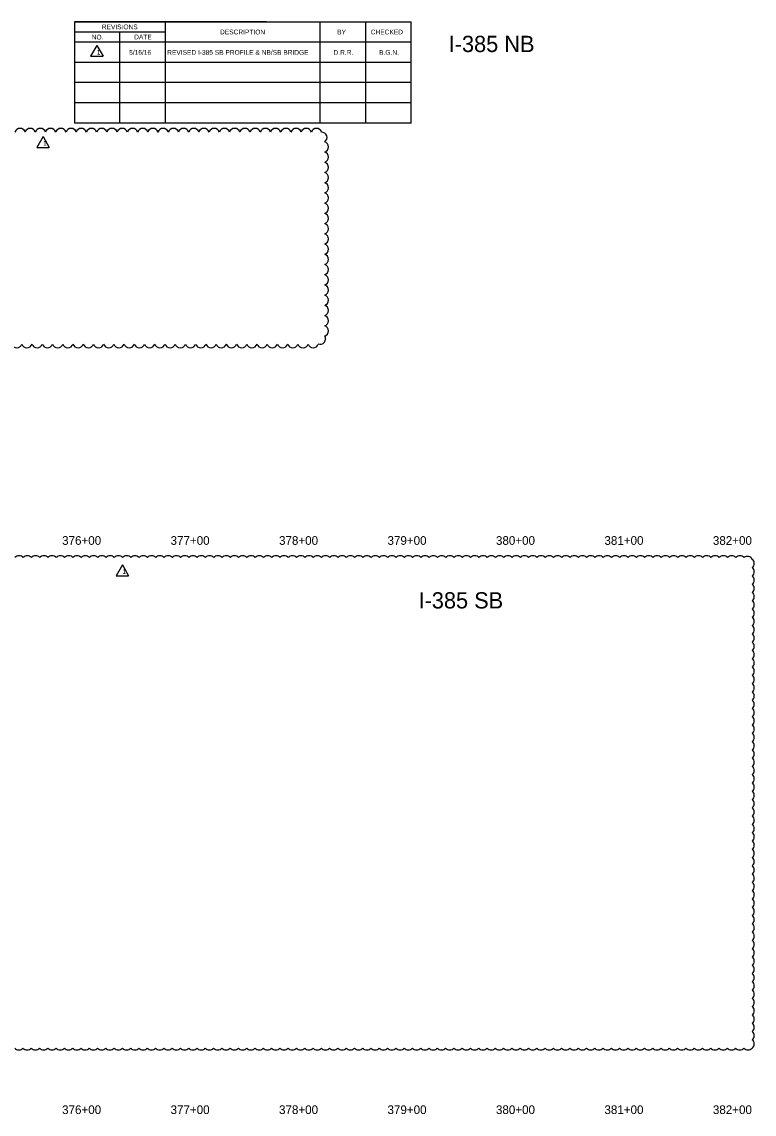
# Model space of a CAD drawing. Extents: x 1617657 to 1619318, y 1076167 to 1077194.
# Drawn here: x 1618080 to 1618756, y 1076167 to 1077175 of the extents above; entities that cross this region are included whole.
import ezdxf

# ---------------------------------------------------------------- set-up
doc = ezdxf.new("R2010")
doc.units = 0
doc.layers.add('Default', color=7, linetype='Continuous')
doc.layers.add('RD_SHT_TX', color=7, linetype='Continuous')

msp = doc.modelspace()

# ---------------------------------------------------------------- linework, layer by layer
at = {"layer": 'RD_SHT_TX'}
for p, q in [((1618128.9, 1077174.7), (1618439.5, 1077174.7)), ((1618306.1, 1077174.7), (1618128.9, 1077174.7)), ((1618128.9, 1077174.7), (1618128.9, 1077081.2)), ((1618212.9, 1077081.2), (1618212.9, 1077174.7)), ((1618355.5, 1077081.2), (1618355.5, 1077174.7)), ((1618397.5, 1077081.2), (1618397.5, 1077174.7)), ((1618439.5, 1077081.2), (1618439.5, 1077174.7)), ((1618212.9, 1077165.3), (1618128.9, 1077165.3)), ((1618170.9, 1077081.2), (1618170.9, 1077165.3)), ((1618439.5, 1077156), (1618128.9, 1077156)), ((1618149.6, 1077153), (1618143.9, 1077142.9)), ((1618149.6, 1077153), (1618155.3, 1077142.9)), ((1618143.9, 1077142.9), (1618155.3, 1077142.9)), ((1618439.5, 1077137.3), (1618128.9, 1077137.3)), ((1618439.5, 1077118.6), (1618128.9, 1077118.6)), ((1618439.5, 1077099.9), (1618128.9, 1077099.9)), ((1618439.5, 1077081.2), (1618128.9, 1077081.2)), ((1618100, 1077068.9), (1618094.3, 1077058.8)), ((1618100, 1077068.9), (1618105.7, 1077058.8)), ((1618094.3, 1077058.8), (1618105.7, 1077058.8)), ((1618173.2, 1076673.9), (1618167.5, 1076663.7)), ((1618173.2, 1076673.9), (1618178.9, 1076663.7)), ((1618167.5, 1076663.7), (1618178.9, 1076663.7))]:
    msp.add_line(p, q, dxfattribs=at)
for centre, radius, start, end in [((1618078.8, 1077071.5), 4.94, 17.5, 162.5), ((1618088.2, 1077071.5), 4.94, 17.5, 162.5), ((1618097.6, 1077071.5), 4.94, 17.5, 162.5), ((1618107, 1077071.5), 4.94, 17.5, 162.5), ((1618116.5, 1077071.5), 4.94, 17.5, 162.5), ((1618125.9, 1077071.5), 4.94, 17.5, 162.5), ((1618135.3, 1077071.5), 4.94, 17.5, 162.5), ((1618144.7, 1077071.5), 4.94, 17.5, 162.5), ((1618154.2, 1077071.5), 4.94, 17.5, 162.5), ((1618163.6, 1077071.5), 4.94, 17.5, 162.5), ((1618173, 1077071.5), 4.94, 17.5, 162.5), ((1618182.5, 1077071.5), 4.94, 17.5, 162.5), ((1618191.9, 1077071.5), 4.94, 17.5, 162.5), ((1618201.3, 1077071.5), 4.94, 17.5, 162.5), ((1618210.7, 1077071.5), 4.94, 17.5, 162.5), ((1618220.2, 1077071.5), 4.94, 17.5, 162.5), ((1618229.6, 1077071.5), 4.94, 17.5, 162.5), ((1618239, 1077071.5), 4.94, 17.5, 162.5), ((1618248.4, 1077071.5), 4.94, 17.5, 162.5), ((1618257.9, 1077071.5), 4.94, 17.5, 162.5), ((1618267.3, 1077071.5), 4.94, 17.5, 162.5), ((1618276.7, 1077071.5), 4.94, 17.5, 162.5), ((1618286.1, 1077071.5), 4.94, 17.5, 162.5), ((1618295.6, 1077071.5), 4.94, 17.5, 162.5), ((1618305, 1077071.5), 4.94, 17.5, 162.5), ((1618314.4, 1077071.5), 4.94, 17.5, 162.5), ((1618323.9, 1077071.5), 4.94, 17.5, 162.5), ((1618333.3, 1077071.5), 4.94, 17.5, 162.5), ((1618342.7, 1077071.5), 4.94, 17.5, 162.5), ((1618352.1, 1077071.5), 4.94, 17.5, 162.5), ((1618356.9, 1077068), 4.94, 305.5066, 90.5066), ((1618358.3, 1077059.3), 4.94, 287.5, 72.5), ((1618358.3, 1077049.9), 4.94, 287.5, 72.5), ((1618358.3, 1077040.4), 4.94, 287.5, 72.5), ((1618358.3, 1077031), 4.94, 287.5, 72.5), ((1618358.3, 1077021.6), 4.94, 287.5, 72.5), ((1618358.3, 1077012.2), 4.94, 287.5, 72.5), ((1618358.3, 1077002.7), 4.94, 287.5, 72.5), ((1618358.3, 1076993.3), 4.94, 287.5, 72.5), ((1618358.3, 1076983.9), 4.94, 287.5, 72.5), ((1618358.3, 1076974.5), 4.94, 287.5, 72.5), ((1618358.3, 1076965), 4.94, 287.5, 72.5), ((1618358.3, 1076955.6), 4.94, 287.5, 72.5), ((1618358.3, 1076946.2), 4.94, 287.5, 72.5), ((1618358.3, 1076936.7), 4.94, 287.5, 72.5), ((1618358.3, 1076927.3), 4.94, 287.5, 72.5), ((1618358.3, 1076917.9), 4.94, 287.5, 72.5), ((1618358.3, 1076908.5), 4.94, 287.5, 72.5), ((1618358.3, 1076899), 4.94, 287.5, 72.5), ((1618358.3, 1076889.6), 4.94, 287.5, 72.5), ((1618355.6, 1076882.2), 4.94, 248.7452, 33.7452), ((1618075.8, 1076879), 4.94, 197.5, 342.5), ((1618085.2, 1076879), 4.94, 197.5, 342.5), ((1618094.6, 1076879), 4.94, 197.5, 342.5), ((1618104.1, 1076879), 4.94, 197.5, 342.5), ((1618113.5, 1076879), 4.94, 197.5, 342.5), ((1618122.9, 1076879), 4.94, 197.5, 342.5), ((1618132.3, 1076879), 4.94, 197.5, 342.5), ((1618141.8, 1076879), 4.94, 197.5, 342.5), ((1618151.2, 1076879), 4.94, 197.5, 342.5), ((1618160.6, 1076879), 4.94, 197.5, 342.5), ((1618170, 1076879), 4.94, 197.5, 342.5), ((1618179.5, 1076879), 4.94, 197.5, 342.5), ((1618188.9, 1076879), 4.94, 197.5, 342.5), ((1618198.3, 1076879), 4.94, 197.5, 342.5), ((1618207.7, 1076879), 4.94, 197.5, 342.5), ((1618217.2, 1076879), 4.94, 197.5, 342.5), ((1618226.6, 1076879), 4.94, 197.5, 342.5), ((1618236, 1076879), 4.94, 197.5, 342.5), ((1618245.5, 1076879), 4.94, 197.5, 342.5), ((1618254.9, 1076879), 4.94, 197.5, 342.5), ((1618264.3, 1076879), 4.94, 197.5, 342.5), ((1618273.7, 1076879), 4.94, 197.5, 342.5), ((1618283.2, 1076879), 4.94, 197.5, 342.5), ((1618292.6, 1076879), 4.94, 197.5, 342.5), ((1618302, 1076879), 4.94, 197.5, 342.5), ((1618311.4, 1076879), 4.94, 197.5, 342.5), ((1618320.9, 1076879), 4.94, 197.5, 342.5), ((1618330.3, 1076879), 4.94, 197.5, 342.5), ((1618339.7, 1076879), 4.94, 197.5, 342.5), ((1618349.1, 1076879), 4.94, 197.5, 342.5), ((1618077.9, 1076677.3), 4.99, 40, 140), ((1618085.5, 1076677.3), 4.99, 40, 140), ((1618093.1, 1076677.3), 4.99, 40, 140), ((1618100.8, 1076677.3), 4.99, 40, 140), ((1618108.4, 1076677.3), 4.99, 40, 140), ((1618116.1, 1076677.3), 4.99, 40, 140), ((1618123.7, 1076677.3), 4.99, 40, 140), ((1618131.3, 1076677.3), 4.99, 40, 140), ((1618139, 1076677.3), 4.99, 40, 140), ((1618146.6, 1076677.3), 4.99, 40, 140), ((1618154.3, 1076677.3), 4.99, 40, 140), ((1618161.9, 1076677.3), 4.99, 40, 140), ((1618169.5, 1076677.3), 4.99, 40, 140), ((1618177.2, 1076677.3), 4.99, 40, 140), ((1618184.8, 1076677.3), 4.99, 40, 140), ((1618192.5, 1076677.3), 4.99, 40, 140), ((1618200.1, 1076677.3), 4.99, 40, 140), ((1618207.7, 1076677.3), 4.99, 40, 140), ((1618215.4, 1076677.3), 4.99, 40, 140), ((1618223, 1076677.3), 4.99, 40, 140), ((1618230.7, 1076677.3), 4.99, 40, 140), ((1618238.3, 1076677.3), 4.99, 40, 140), ((1618245.9, 1076677.3), 4.99, 40, 140), ((1618253.6, 1076677.3), 4.99, 40, 140), ((1618261.2, 1076677.3), 4.99, 40, 140), ((1618268.9, 1076677.3), 4.99, 40, 140), ((1618276.5, 1076677.3), 4.99, 40, 140), ((1618284.1, 1076677.3), 4.99, 40, 140), ((1618291.8, 1076677.3), 4.99, 40, 140), ((1618299.4, 1076677.3), 4.99, 40, 140), ((1618307.1, 1076677.3), 4.99, 40, 140), ((1618314.7, 1076677.3), 4.99, 40, 140), ((1618322.3, 1076677.3), 4.99, 40, 140), ((1618330, 1076677.3), 4.99, 40, 140), ((1618337.6, 1076677.3), 4.99, 40, 140), ((1618345.3, 1076677.3), 4.99, 40, 140), ((1618352.9, 1076677.3), 4.99, 40, 140), ((1618360.5, 1076677.3), 4.99, 40, 140), ((1618368.2, 1076677.3), 4.99, 40, 140), ((1618375.8, 1076677.3), 4.99, 40, 140), ((1618383.5, 1076677.3), 4.99, 40, 140), ((1618391.1, 1076677.3), 4.99, 40, 140), ((1618398.7, 1076677.3), 4.99, 40, 140), ((1618406.4, 1076677.3), 4.99, 40, 140), ((1618414, 1076677.3), 4.99, 40, 140), ((1618421.7, 1076677.3), 4.99, 40, 140), ((1618429.3, 1076677.3), 4.99, 40, 140), ((1618436.9, 1076677.3), 4.99, 40, 140), ((1618444.6, 1076677.3), 4.99, 40, 140), ((1618452.2, 1076677.3), 4.99, 40, 140), ((1618459.9, 1076677.3), 4.99, 40, 140), ((1618467.5, 1076677.3), 4.99, 40, 140), ((1618475.1, 1076677.3), 4.99, 40, 140), ((1618482.8, 1076677.3), 4.99, 40, 140), ((1618490.4, 1076677.3), 4.99, 40, 140), ((1618498.1, 1076677.3), 4.99, 40, 140), ((1618505.7, 1076677.3), 4.99, 40, 140), ((1618513.3, 1076677.3), 4.99, 40, 140), ((1618521, 1076677.3), 4.99, 40, 140), ((1618528.6, 1076677.3), 4.99, 40, 140), ((1618536.3, 1076677.3), 4.99, 40, 140), ((1618543.9, 1076677.3), 4.99, 40, 140), ((1618551.5, 1076677.3), 4.99, 40, 140), ((1618559.2, 1076677.3), 4.99, 40, 140), ((1618566.8, 1076677.3), 4.99, 40, 140), ((1618574.5, 1076677.3), 4.99, 40, 140), ((1618582.1, 1076677.3), 4.99, 40, 140), ((1618589.8, 1076677.3), 4.99, 40, 140), ((1618597.4, 1076677.3), 4.99, 40, 140), ((1618605, 1076677.3), 4.99, 40, 140), ((1618612.7, 1076677.3), 4.99, 40, 140), ((1618620.3, 1076677.3), 4.99, 40, 140), ((1618628, 1076677.3), 4.99, 40, 140), ((1618635.6, 1076677.3), 4.99, 40, 140), ((1618643.2, 1076677.3), 4.99, 40, 140), ((1618650.9, 1076677.3), 4.99, 40, 140), ((1618658.5, 1076677.3), 4.99, 40, 140), ((1618666.2, 1076677.3), 4.99, 40, 140), ((1618673.8, 1076677.3), 4.99, 40, 140), ((1618681.4, 1076677.3), 4.99, 40, 140), ((1618689.1, 1076677.3), 4.99, 40, 140), ((1618696.7, 1076677.3), 4.99, 40, 140), ((1618704.4, 1076677.3), 4.99, 40, 140), ((1618712, 1076677.3), 4.99, 40, 140), ((1618719.6, 1076677.3), 4.99, 40, 140), ((1618727.3, 1076677.3), 4.99, 40, 140), ((1618734.9, 1076677.3), 4.99, 40, 140), ((1618742.6, 1076677.3), 4.99, 40, 140), ((1618749.5, 1076676.6), 4.99, 28.2006, 128.2006), ((1618750.7, 1076675.1), 4.99, 310, 50), ((1618750.7, 1076667.5), 4.99, 310, 50), ((1618750.7, 1076659.8), 4.99, 310, 50), ((1618750.7, 1076652.2), 4.99, 310, 50), ((1618750.7, 1076644.6), 4.99, 310, 50), ((1618750.7, 1076636.9), 4.99, 310, 50), ((1618750.7, 1076629.3), 4.99, 310, 50), ((1618750.7, 1076621.6), 4.99, 310, 50), ((1618750.7, 1076614), 4.99, 310, 50), ((1618750.7, 1076606.4), 4.99, 310, 50), ((1618750.7, 1076598.7), 4.99, 310, 50), ((1618750.7, 1076591.1), 4.99, 310, 50), ((1618750.7, 1076583.4), 4.99, 310, 50), ((1618750.7, 1076575.8), 4.99, 310, 50), ((1618750.7, 1076568.2), 4.99, 310, 50), ((1618750.7, 1076560.5), 4.99, 310, 50), ((1618750.7, 1076552.9), 4.99, 310, 50), ((1618750.7, 1076545.2), 4.99, 310, 50), ((1618750.7, 1076537.6), 4.99, 310, 50), ((1618750.7, 1076530), 4.99, 310, 50), ((1618750.7, 1076522.3), 4.99, 310, 50), ((1618750.7, 1076514.7), 4.99, 310, 50), ((1618750.7, 1076507), 4.99, 310, 50), ((1618750.7, 1076499.4), 4.99, 310, 50), ((1618750.7, 1076491.8), 4.99, 310, 50), ((1618750.7, 1076484.1), 4.99, 310, 50), ((1618750.7, 1076476.5), 4.99, 310, 50), ((1618750.7, 1076468.8), 4.99, 310, 50), ((1618750.7, 1076461.2), 4.99, 310, 50), ((1618750.7, 1076453.6), 4.99, 310, 50), ((1618750.7, 1076445.9), 4.99, 310, 50), ((1618750.7, 1076438.3), 4.99, 310, 50), ((1618750.7, 1076430.6), 4.99, 310, 50), ((1618750.7, 1076423), 4.99, 310, 50), ((1618750.7, 1076415.4), 4.99, 310, 50), ((1618750.7, 1076407.7), 4.99, 310, 50), ((1618750.7, 1076400.1), 4.99, 310, 50), ((1618750.7, 1076392.4), 4.99, 310, 50), ((1618750.7, 1076384.8), 4.99, 310, 50), ((1618750.7, 1076377.2), 4.99, 310, 50), ((1618750.7, 1076369.5), 4.99, 310, 50), ((1618750.7, 1076361.9), 4.99, 310, 50), ((1618750.7, 1076354.2), 4.99, 310, 50), ((1618750.7, 1076346.6), 4.99, 310, 50), ((1618750.7, 1076339), 4.99, 310, 50), ((1618750.7, 1076331.3), 4.99, 310, 50), ((1618750.7, 1076323.7), 4.99, 310, 50), ((1618750.7, 1076316), 4.99, 310, 50), ((1618750.7, 1076308.4), 4.99, 310, 50), ((1618750.7, 1076300.8), 4.99, 310, 50), ((1618750.7, 1076293.1), 4.99, 310, 50), ((1618750.7, 1076285.5), 4.99, 310, 50), ((1618750.7, 1076277.8), 4.99, 310, 50), ((1618750.7, 1076270.2), 4.99, 310, 50), ((1618750.7, 1076262.6), 4.99, 310, 50), ((1618750.7, 1076254.9), 4.99, 310, 50), ((1618750.7, 1076247.3), 4.99, 310, 50), ((1618750.7, 1076239.6), 4.99, 310, 50), ((1618750.7, 1076232), 4.99, 310, 50), ((1618077.7, 1076231.4), 4.99, 220, 320), ((1618085.3, 1076231.4), 4.99, 220, 320), ((1618093, 1076231.4), 4.99, 220, 320), ((1618100.6, 1076231.4), 4.99, 220, 320), ((1618108.3, 1076231.4), 4.99, 220, 320), ((1618115.9, 1076231.4), 4.99, 220, 320), ((1618123.5, 1076231.4), 4.99, 220, 320), ((1618131.2, 1076231.4), 4.99, 220, 320), ((1618138.8, 1076231.4), 4.99, 220, 320), ((1618146.5, 1076231.4), 4.99, 220, 320), ((1618154.1, 1076231.4), 4.99, 220, 320), ((1618161.7, 1076231.4), 4.99, 220, 320), ((1618169.4, 1076231.4), 4.99, 220, 320), ((1618177, 1076231.4), 4.99, 220, 320), ((1618184.7, 1076231.4), 4.99, 220, 320), ((1618192.3, 1076231.4), 4.99, 220, 320), ((1618200, 1076231.4), 4.99, 220, 320), ((1618207.6, 1076231.4), 4.99, 220, 320), ((1618215.2, 1076231.4), 4.99, 220, 320), ((1618222.9, 1076231.4), 4.99, 220, 320), ((1618230.5, 1076231.4), 4.99, 220, 320), ((1618238.2, 1076231.4), 4.99, 220, 320), ((1618245.8, 1076231.4), 4.99, 220, 320), ((1618253.4, 1076231.4), 4.99, 220, 320), ((1618261.1, 1076231.4), 4.99, 220, 320), ((1618268.7, 1076231.4), 4.99, 220, 320), ((1618276.4, 1076231.4), 4.99, 220, 320), ((1618284, 1076231.4), 4.99, 220, 320), ((1618291.6, 1076231.4), 4.99, 220, 320), ((1618299.3, 1076231.4), 4.99, 220, 320), ((1618306.9, 1076231.4), 4.99, 220, 320), ((1618314.6, 1076231.4), 4.99, 220, 320), ((1618322.2, 1076231.4), 4.99, 220, 320), ((1618329.8, 1076231.4), 4.99, 220, 320), ((1618337.5, 1076231.4), 4.99, 220, 320), ((1618345.1, 1076231.4), 4.99, 220, 320), ((1618352.8, 1076231.4), 4.99, 220, 320), ((1618360.4, 1076231.4), 4.99, 220, 320), ((1618368, 1076231.4), 4.99, 220, 320), ((1618375.7, 1076231.4), 4.99, 220, 320), ((1618383.3, 1076231.4), 4.99, 220, 320), ((1618391, 1076231.4), 4.99, 220, 320), ((1618398.6, 1076231.4), 4.99, 220, 320), ((1618406.2, 1076231.4), 4.99, 220, 320), ((1618413.9, 1076231.4), 4.99, 220, 320), ((1618421.5, 1076231.4), 4.99, 220, 320), ((1618429.2, 1076231.4), 4.99, 220, 320), ((1618436.8, 1076231.4), 4.99, 220, 320), ((1618444.4, 1076231.4), 4.99, 220, 320), ((1618452.1, 1076231.4), 4.99, 220, 320), ((1618459.7, 1076231.4), 4.99, 220, 320), ((1618467.4, 1076231.4), 4.99, 220, 320), ((1618475, 1076231.4), 4.99, 220, 320), ((1618482.6, 1076231.4), 4.99, 220, 320), ((1618490.3, 1076231.4), 4.99, 220, 320), ((1618497.9, 1076231.4), 4.99, 220, 320), ((1618505.6, 1076231.4), 4.99, 220, 320), ((1618513.2, 1076231.4), 4.99, 220, 320), ((1618520.8, 1076231.4), 4.99, 220, 320), ((1618528.5, 1076231.4), 4.99, 220, 320), ((1618536.1, 1076231.4), 4.99, 220, 320), ((1618543.8, 1076231.4), 4.99, 220, 320), ((1618551.4, 1076231.4), 4.99, 220, 320), ((1618559, 1076231.4), 4.99, 220, 320), ((1618566.7, 1076231.4), 4.99, 220, 320), ((1618574.3, 1076231.4), 4.99, 220, 320), ((1618582, 1076231.4), 4.99, 220, 320), ((1618589.6, 1076231.4), 4.99, 220, 320), ((1618597.2, 1076231.4), 4.99, 220, 320), ((1618604.9, 1076231.4), 4.99, 220, 320), ((1618612.5, 1076231.4), 4.99, 220, 320), ((1618620.2, 1076231.4), 4.99, 220, 320), ((1618627.8, 1076231.4), 4.99, 220, 320), ((1618635.4, 1076231.4), 4.99, 220, 320), ((1618643.1, 1076231.4), 4.99, 220, 320), ((1618650.7, 1076231.4), 4.99, 220, 320), ((1618658.4, 1076231.4), 4.99, 220, 320), ((1618666, 1076231.4), 4.99, 220, 320), ((1618673.6, 1076231.4), 4.99, 220, 320), ((1618681.3, 1076231.4), 4.99, 220, 320), ((1618688.9, 1076231.4), 4.99, 220, 320), ((1618696.6, 1076231.4), 4.99, 220, 320), ((1618704.2, 1076231.4), 4.99, 220, 320), ((1618711.8, 1076231.4), 4.99, 220, 320), ((1618719.5, 1076231.4), 4.99, 220, 320), ((1618727.1, 1076231.4), 4.99, 220, 320), ((1618734.8, 1076231.4), 4.99, 220, 320), ((1618742.4, 1076231.4), 4.99, 220, 320), ((1618750, 1076231.4), 4.99, 220, 320)]:
    msp.add_arc(centre, radius, start, end, dxfattribs=at)

# ---------------------------------------------------------------- texts
at = {"layer": 'Default'}
for s, p in [('376+00', (1618117.6, 1076692.3)), ('377+00', (1618217.6, 1076692.3)), ('378+00', (1618317.6, 1076692.3)), ('379+00', (1618417.6, 1076692.3)), ('380+00', (1618517.6, 1076692.3)), ('381+00', (1618617.6, 1076692.3)), ('382+00', (1618717.6, 1076692.3)), ('376+00', (1618117.6, 1076167.3)), ('377+00', (1618217.6, 1076167.3)), ('378+00', (1618317.6, 1076167.3)), ('379+00', (1618417.6, 1076167.3)), ('380+00', (1618517.6, 1076167.3)), ('381+00', (1618617.6, 1076167.3)), ('382+00', (1618717.6, 1076167.3))]:
    msp.add_text(s, height=8, dxfattribs=at).set_placement(p)
at = {"layer": 'RD_SHT_TX'}
for s, height, p in [('NO.', 4.4, (1618144.9, 1077158.4)), ('REVISIONS', 4.4, (1618154.2, 1077167.8)), ('CHECKED', 4.4, (1618402.2, 1077163.1)), ('I-385 NB', 15, (1618474, 1077146.8)), ('1', 4.4, (1618149.6, 1077144.5)), ('5/16/16', 4.4, (1618179.4, 1077144.3)), ('REVISED I-385 SB PROFILE & NB/SB BRIDGE', 4.4, (1618214.5, 1077144.3)), ('D.R.R.', 4.4, (1618367.8, 1077144.3)), ('B.G.N.', 4.4, (1618409.9, 1077144.3)), ('1', 4.4, (1618100, 1077060.4)), ('1', 4.4, (1618173.2, 1076665.4)), ('I-385 SB', 15, (1618446.2, 1076633.6))]:
    msp.add_text(s, height=height, dxfattribs=at).set_placement(p)
for s, height, p in [('DATE', 4.41, (1618184, 1077158.5)), ('DESCRIPTION', 4.408, (1618263.2, 1077163.2)), ('BY', 4.41, (1618371.2, 1077163.1))]:
    msp.add_text(s, height=height, rotation=359.7246, dxfattribs=at).set_placement(p)

doc.saveas('drawing.dxf')
